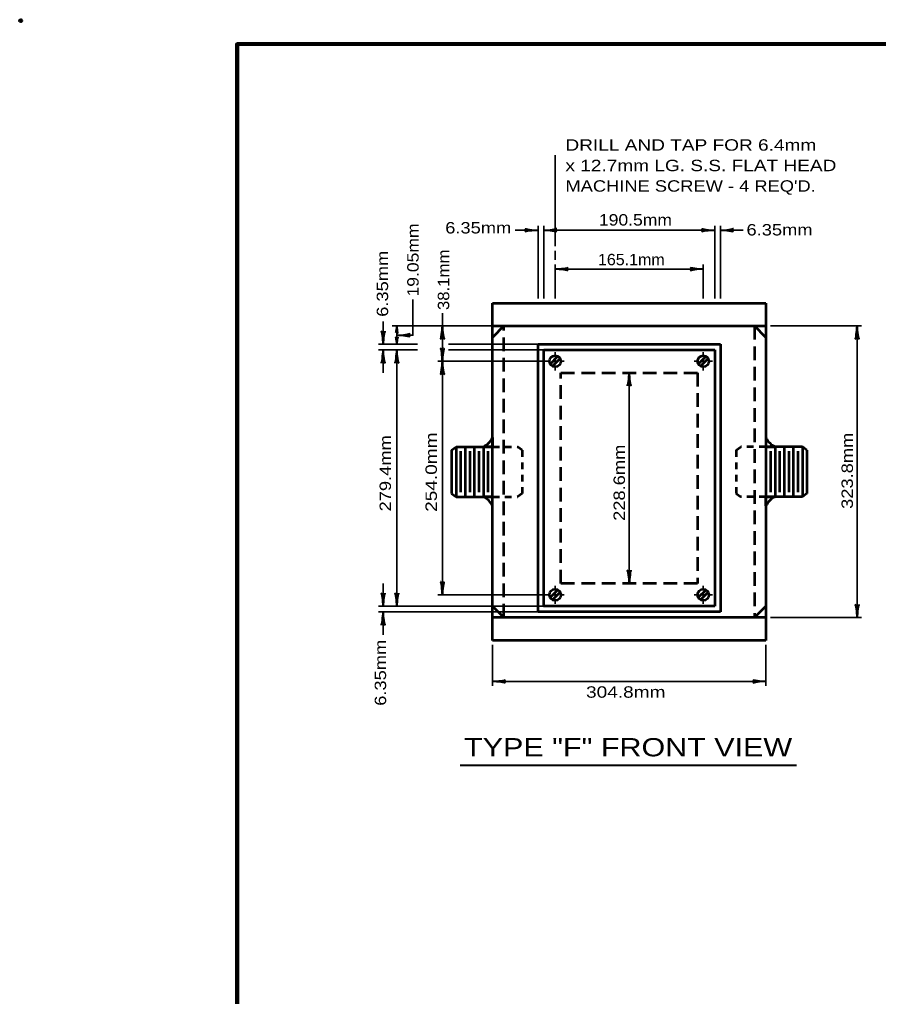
# Model space of a CAD drawing. Extents: x -40 to 816, y -10 to 535.
# Drawn here: x -39.7 to 186.5, y 277.2 to 534.5 of the extents above; entities that cross this region are included whole.
import ezdxf
from ezdxf.enums import TextEntityAlignment as Align

# ---------------------------------------------------------------- set-up
doc = ezdxf.new("R2010")
doc.units = 0
doc.header["$LTSCALE"] = 1.2
doc.header["$PDMODE"] = 32
doc.header["$PDSIZE"] = 0.6
doc.linetypes.add('MEDIUM_DASHED', pattern=[4.5, 3, -1.5])
doc.linetypes.add('SHORT_DASHED', pattern=[2.7, 1.5, -1.2])
doc.layers.add('1', color=7, linetype='Continuous', lineweight=53)

msp = doc.modelspace()

# ---------------------------------------------------------------- linework, layer by layer
at = {"layer": '1', "lineweight": 35}
for p, q in [((101.329, 474.805), (101.329, 498.805)), ((96.829, 479.005), (90.829, 479.005)), ((96.829, 461.005), (96.829, 480.205)), ((98.329, 461.005), (98.329, 480.205)), ((98.329, 479.005), (143.329, 479.005)), ((143.329, 461.005), (143.329, 480.205)), ((144.829, 461.005), (144.829, 480.205)), ((144.829, 479.005), (150.829, 479.005)), ((101.329, 471.205), (101.329, 473.605)), ((101.329, 461.005), (101.329, 470.005)), ((101.329, 468.805), (140.329, 468.805)), ((140.329, 461.005), (140.329, 470.005)), ((56.029, 455.005), (56.029, 449.005)), ((84.829, 453.805), (58.429, 453.805)), ((59.629, 453.805), (59.629, 449.005)), ((158.029, 453.805), (182.029, 453.805)), ((180.829, 453.805), (180.829, 377.005)), ((65.102, 449.005), (54.829, 449.005)), ((96.829, 449.005), (73.203, 449.005)), ((65.102, 447.505), (54.829, 447.505)), ((56.029, 447.505), (56.029, 441.505)), ((59.629, 447.505), (59.629, 380.005)), ((98.329, 447.505), (73.203, 447.505)), ((101.329, 445.705), (101.329, 446.905)), ((140.329, 445.705), (140.329, 446.905)), ((98.929, 444.505), (70.429, 444.505)), ((100.129, 444.505), (98.929, 444.505)), ((100.729, 444.505), (101.929, 444.505)), ((101.329, 443.905), (101.329, 445.105)), ((101.329, 443.305), (101.329, 442.105)), ((102.529, 444.505), (103.729, 444.505)), ((139.129, 444.505), (137.929, 444.505)), ((139.729, 444.505), (140.929, 444.505)), ((140.329, 445.105), (140.329, 443.905)), ((140.329, 443.305), (140.329, 442.105)), ((141.529, 444.505), (142.729, 444.505)), ((120.829, 386.005), (120.829, 441.505)), ((56.029, 386.005), (56.029, 380.005)), ((101.329, 384.205), (101.329, 385.405)), ((101.329, 382.405), (101.329, 383.605)), ((140.329, 384.205), (140.329, 385.405)), ((140.329, 383.605), (140.329, 382.405)), ((98.929, 383.005), (70.429, 383.005)), ((100.129, 383.005), (98.929, 383.005)), ((101.929, 383.005), (100.729, 383.005)), ((101.329, 381.805), (101.329, 380.605)), ((102.529, 383.005), (103.729, 383.005)), ((139.129, 383.005), (137.929, 383.005)), ((139.729, 383.005), (140.929, 383.005)), ((140.329, 381.805), (140.329, 380.605)), ((141.529, 383.005), (142.729, 383.005)), ((98.329, 380.005), (54.829, 380.005)), ((96.829, 378.505), (54.829, 378.505)), ((56.029, 378.505), (56.029, 372.505)), ((158.029, 377.005), (182.029, 377.005)), ((84.829, 369.805), (84.829, 359.005)), ((156.829, 369.805), (156.829, 359.005)), ((84.829, 360.205), (156.829, 360.205))]:
    msp.add_line(p, q, dxfattribs=at)
at = {"layer": '1'}
for p, q in [((84.829, 459.805), (156.829, 459.805)), ((84.829, 453.805), (84.829, 459.805)), ((156.829, 459.805), (156.829, 453.805)), ((84.829, 453.805), (156.829, 453.805)), ((84.829, 422.011), (84.829, 453.805)), ((96.829, 378.505), (96.829, 449.005)), ((96.829, 449.005), (144.829, 449.005)), ((144.829, 449.005), (144.829, 378.505)), ((98.329, 447.505), (143.329, 447.505)), ((100.012, 443.788), (102.047, 445.823)), ((102.647, 445.223), (100.612, 443.188)), ((139.012, 443.788), (141.047, 445.823)), ((141.647, 445.223), (139.612, 443.188)), ((143.329, 447.505), (143.329, 380.005)), ((74.029, 421.105), (75.229, 422.005)), ((75.229, 422.005), (84.805, 422.005)), ((75.229, 422.005), (75.229, 408.805)), ((77.629, 422.005), (77.629, 408.805)), ((80.029, 422.005), (80.029, 408.805)), ((82.429, 422.005), (82.429, 408.805)), ((84.829, 380.005), (84.829, 422.005)), ((166.429, 422.005), (156.829, 422.005)), ((159.229, 422.005), (159.229, 408.805)), ((161.629, 422.005), (161.629, 408.805)), ((164.029, 422.005), (164.029, 408.805)), ((166.429, 422.005), (166.429, 408.805)), ((167.629, 421.105), (166.429, 422.005)), ((74.029, 421.105), (74.029, 409.705)), ((76.429, 420.805), (76.429, 410.005)), ((78.829, 420.805), (78.829, 410.005)), ((81.229, 420.805), (81.229, 410.005)), ((83.629, 420.805), (83.629, 410.005)), ((158.029, 420.805), (158.029, 410.005)), ((160.429, 420.805), (160.429, 410.005)), ((162.829, 420.805), (162.829, 410.005)), ((165.229, 420.805), (165.229, 410.005)), ((167.629, 421.105), (167.629, 409.705)), ((74.029, 409.705), (75.229, 408.805)), ((167.629, 409.705), (166.429, 408.805)), ((75.229, 408.805), (84.829, 408.805)), ((166.429, 408.805), (156.829, 408.805)), ((100.012, 382.288), (102.047, 384.323)), ((102.647, 383.723), (100.612, 381.688)), ((139.012, 382.288), (141.047, 384.323)), ((139.612, 381.688), (141.647, 383.723)), ((84.829, 371.005), (84.829, 380.005)), ((144.829, 378.505), (96.829, 378.505)), ((156.829, 377.005), (84.829, 377.005)), ((156.829, 371.005), (84.829, 371.005))]:
    msp.add_line(p, q, dxfattribs=at)
at = {"layer": '1', "linetype": 'MEDIUM_DASHED'}
for p, q in [((87.829, 377.005), (87.829, 453.805)), ((153.829, 453.805), (153.829, 377.005)), ((102.829, 386.005), (102.829, 441.505)), ((102.829, 441.505), (138.829, 441.505))]:
    msp.add_line(p, q, dxfattribs=at)
at = {"layer": '1', "linetype": 'SHORT_DASHED'}
for p, q in [((84.829, 422.005), (91.429, 422.005)), ((92.629, 421.105), (91.429, 422.005)), ((149.029, 421.105), (150.229, 422.005)), ((156.829, 422.005), (150.229, 422.005)), ((92.629, 421.105), (92.629, 409.705)), ((149.029, 421.105), (149.029, 409.705)), ((92.629, 409.705), (91.429, 408.805)), ((149.029, 409.705), (150.229, 408.805)), ((84.829, 408.805), (91.429, 408.805)), ((156.829, 408.805), (150.229, 408.805))]:
    msp.add_line(p, q, dxfattribs=at)
at = {"layer": '1', "lineweight": 40}
msp.add_line((76.282, 338.143), (164.843, 338.143), dxfattribs=at)
at = {"layer": '1', "lineweight": 158}
msp.add_lwpolyline([(809.296, 528.117), (17.596, 528.017), (17.696, 2.017)], dxfattribs=at)
at = {"layer": '1', "lineweight": 35}
for points in [[(59.695, 451.36), (63.878, 451.36), (63.878, 460.776)], [(71.629, 457.18), (71.629, 444.505), (71.629, 383.005)]]:
    msp.add_lwpolyline(points, dxfattribs=at)
at = {"layer": '1'}
for points in [[(84.829, 453.805), (87.829, 453.805), (84.829, 450.805)], [(153.829, 453.805), (156.829, 453.805), (156.829, 450.805)], [(84.829, 377.005), (84.829, 380.005), (87.829, 377.005)], [(156.829, 377.005), (153.829, 377.005), (156.829, 380.005)]]:
    msp.add_lwpolyline(points, close=True, dxfattribs=at)
for points in [[(156.829, 453.805), (156.829, 380.005), (156.829, 371.005)], [(143.329, 380.005), (98.329, 380.005), (98.329, 447.505)], [(84.829, 424.405), (84.829, 422.005), (82.429, 422.005)], [(156.829, 424.405), (156.829, 422.005), (159.229, 422.005)], [(84.829, 406.405), (84.829, 408.805), (82.429, 408.805)], [(156.829, 406.405), (156.829, 408.805), (159.229, 408.805)]]:
    msp.add_lwpolyline(points, dxfattribs=at)
at = {"layer": '1', "linetype": 'MEDIUM_DASHED'}
msp.add_lwpolyline([(138.829, 441.505), (138.829, 386.005), (102.829, 386.005)], dxfattribs=at)
at = {"layer": '1'}
for centre in [(101.329, 444.505), (140.329, 444.505), (101.329, 383.005), (140.329, 383.005)]:
    msp.add_circle(centre, 1.5, dxfattribs=at)
for centre, start, end in [((80.173, 426.662), 295.85509, 334.14491), ((161.486, 426.662), 205.85509, 244.14491), ((80.173, 404.149), 25.85509, 64.14491), ((161.486, 404.149), 115.85509, 154.14491)]:
    msp.add_arc(centre, 5.175, start, end, dxfattribs=at)
at = {"layer": '1', "lineweight": 40}
for centre, major_axis, ratio, start_param, end_param in [((95.52, 478.674), (2.143, 0.187), 0.122415, 0.8963533, 3.1415927), ((95.485, 479.259), (2.108, -0.211), 0.07063, 3.1407148, 5.41811), ((99.674, 478.751), (-2.108, 0.211), 0.07063, 3.1407148, 5.41811), ((99.674, 478.751), (-2.108, 0.211), 0.07063, 3.1407148, 5.41811), ((99.639, 479.337), (-2.143, -0.187), 0.122415, 0.8963533, 3.1415927), ((99.639, 479.337), (-2.143, -0.187), 0.122415, 0.8963533, 3.1415927), ((142.02, 478.674), (2.143, 0.187), 0.122415, 0.8963533, 3.1415927), ((141.985, 479.259), (2.108, -0.211), 0.07063, 3.1407148, 5.41811), ((146.174, 478.751), (-2.108, 0.211), 0.07063, 3.1407148, 5.41811), ((146.139, 479.337), (-2.143, -0.187), 0.122415, 0.8963533, 3.1415927), ((102.674, 468.551), (-2.108, 0.211), 0.07063, 3.1407148, 5.41811), ((102.639, 469.137), (-2.143, -0.187), 0.122415, 0.8963533, 3.1415927), ((139.02, 468.474), (2.143, 0.187), 0.122415, 0.8963533, 3.1415927), ((139.02, 468.474), (2.143, 0.187), 0.122415, 0.8963533, 3.1415927), ((138.985, 469.059), (2.108, -0.211), 0.07063, 3.1407148, 5.41811), ((138.985, 469.059), (2.108, -0.211), 0.07063, 3.1407148, 5.41811), ((59.559, 454.092), (0.211, 2.108), 0.07063, 3.1407148, 4.1144709), ((59.302, 452.927), (0.187, 2.143), 0.122415, 4.7072452, 5.1459979), ((59.946, 452.927), (-0.187, 2.143), 0.122415, 1.1378214, 1.5759401), ((59.795, 454.127), (-0.187, 2.143), 0.122415, 2.1736985, 3.1415927), ((71.375, 452.461), (0.211, 2.108), 0.07063, 3.1407148, 5.41811), ((71.961, 452.496), (-0.187, 2.143), 0.122415, 0.8963533, 3.1415927), ((180.575, 452.461), (0.211, 2.108), 0.07063, 3.1407148, 5.41811), ((180.575, 452.461), (0.211, 2.108), 0.07063, 3.1407148, 5.41811), ((181.161, 452.496), (-0.187, 2.143), 0.122415, 0.8963533, 3.1415927), ((181.161, 452.496), (-0.187, 2.143), 0.122415, 0.8963533, 3.1415927), ((55.698, 450.315), (0.187, -2.143), 0.122415, 0.8963533, 3.1415927), ((56.283, 450.35), (-0.211, -2.108), 0.07063, 3.1407148, 5.41811), ((59.464, 448.684), (0.187, -2.143), 0.122415, 2.1736985, 3.1415927), ((61.039, 451.106), (-2.108, 0.211), 0.07063, 3.1407148, 5.41811), ((61.004, 451.692), (-2.143, -0.187), 0.122415, 0.8963533, 3.1415927), ((59.699, 448.719), (-0.211, -2.108), 0.07063, 3.1407148, 4.1144709), ((59.313, 449.884), (0.187, -2.143), 0.122415, 1.1378214, 1.5759401), ((59.956, 449.884), (-0.187, -2.143), 0.122415, 4.7072452, 5.1459979), ((71.298, 445.815), (0.187, -2.143), 0.122415, 0.8963533, 3.1415927), ((71.883, 445.85), (-0.211, -2.108), 0.07063, 3.1407148, 5.41811), ((55.775, 446.161), (0.211, 2.108), 0.07063, 3.1407148, 5.41811), ((56.361, 446.196), (-0.187, 2.143), 0.122415, 0.8963533, 3.1415927), ((59.375, 446.161), (0.211, 2.108), 0.07063, 3.1407148, 5.41811), ((59.961, 446.196), (-0.187, 2.143), 0.122415, 0.8963533, 3.1415927), ((71.375, 443.161), (0.211, 2.108), 0.07063, 3.1407148, 5.41811), ((71.961, 443.196), (-0.187, 2.143), 0.122415, 0.8963533, 3.1415927), ((120.575, 440.161), (0.211, 2.108), 0.07063, 3.1407148, 5.41811), ((120.575, 440.161), (0.211, 2.108), 0.07063, 3.1407148, 5.41811), ((121.161, 440.196), (-0.187, 2.143), 0.122415, 0.8963533, 3.1415927), ((121.161, 440.196), (-0.187, 2.143), 0.122415, 0.8963533, 3.1415927), ((120.498, 387.315), (0.187, -2.143), 0.122415, 0.8963533, 3.1415927), ((121.083, 387.35), (-0.211, -2.108), 0.07063, 3.1407148, 5.41811), ((71.298, 384.315), (0.187, -2.143), 0.122415, 0.8963533, 3.1415927), ((71.883, 384.35), (-0.211, -2.108), 0.07063, 3.1407148, 5.41811), ((55.698, 381.315), (0.187, -2.143), 0.122415, 0.8963533, 3.1415927), ((56.283, 381.35), (-0.211, -2.108), 0.07063, 3.1407148, 5.41811), ((59.298, 381.315), (0.187, -2.143), 0.122415, 0.8963533, 3.1415927), ((59.883, 381.35), (-0.211, -2.108), 0.07063, 3.1407148, 5.41811), ((55.775, 377.161), (0.211, 2.108), 0.07063, 3.1407148, 5.41811), ((56.361, 377.196), (-0.187, 2.143), 0.122415, 0.8963533, 3.1415927), ((180.498, 378.315), (0.187, -2.143), 0.122415, 0.8963533, 3.1415927), ((180.498, 378.315), (0.187, -2.143), 0.122415, 0.8963533, 3.1415927), ((181.083, 378.35), (-0.211, -2.108), 0.07063, 3.1407148, 5.41811), ((181.083, 378.35), (-0.211, -2.108), 0.07063, 3.1407148, 5.41811), ((86.139, 360.537), (-2.143, -0.187), 0.122415, 0.8963533, 3.1415927), ((86.139, 360.537), (-2.143, -0.187), 0.122415, 0.8963533, 3.1415927), ((155.485, 360.459), (2.108, -0.211), 0.07063, 3.1407148, 5.41811), ((86.174, 359.951), (-2.108, 0.211), 0.07063, 3.1407148, 5.41811), ((86.174, 359.951), (-2.108, 0.211), 0.07063, 3.1407148, 5.41811), ((155.52, 359.874), (2.143, 0.187), 0.122415, 0.8963533, 3.1415927)]:
    msp.add_ellipse(centre, major_axis=major_axis, ratio=ratio, start_param=start_param, end_param=end_param, dxfattribs=at)
at = {"layer": '1'}
msp.add_point((-39.404, 534.217), dxfattribs=at)

# ---------------------------------------------------------------- texts
for s, width, p in [('DRILL AND TAP FOR 6.4mm', 1.25, (104.038, 499.98)), ('x 12.7mm LG. S.S. FLAT HEAD', 1.25, (104.038, 494.58)), ("MACHINE SCREW - 4 REQ'D.", 1.2, (104.038, 489.18))]:
    msp.add_text(s, height=3, dxfattribs=dict(at, width=width)).set_placement(p)
for s, height, width, p in [('6.35mm', 3, 1.2, (81.075, 478.175)), ('190.5mm', 3, 1.15, (122.468, 480.258)), ('6.35mm', 3, 1.2, (160.405, 477.646)), ('165.1mm', 3, 1.05, (121.385, 469.805)), ('304.8mm', 3, 1.25, (119.911, 355.904)), ('TYPE "F" FRONT VIEW', 4.8, 1.25, (120.542, 340.463))]:
    msp.add_text(s, height=height, dxfattribs=dict(at, width=width)).set_placement(p, align=Align.CENTER)
for s, width, p in [('19.05mm', 1.15, (65.381, 471.191)), ('38.1mm', 1.1, (73.428, 465.967)), ('6.35mm', 1.2, (57.342, 464.921)), ('279.4mm', 1.2, (58.104, 414.999)), ('254.0mm', 1.25, (70.189, 415.302)), ('323.8mm', 1.2, (179.728, 415.664)), ('228.6mm', 1.2, (119.705, 412.512)), ('6.35mm', 1.2, (56.813, 362.472))]:
    msp.add_text(s, height=3, rotation=90, dxfattribs=dict(at, width=width)).set_placement(p, align=Align.CENTER)

doc.saveas('drawing.dxf')
